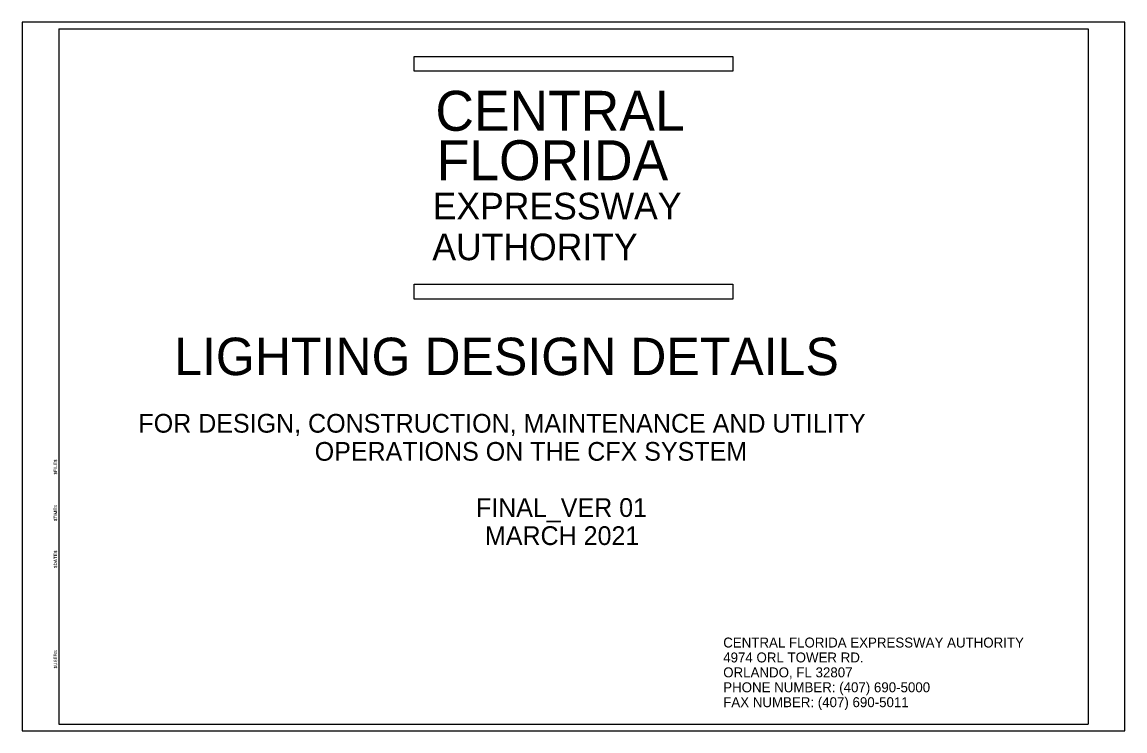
# Model space of a CAD drawing. Extents: x 1888.7 to 1905.2, y -90 to -79.4.
import ezdxf

# ---------------------------------------------------------------- set-up
doc = ezdxf.new("R2010")
doc.units = 0
for name, color, linetype in [('PlotBorder_dp', 7, 'Continuous'), ('SheetBorder_dp', 7, 'Continuous'), ('SignPanel', 7, 'Continuous'), ('TextLabel', 7, 'Continuous'), ('TextMisc', 7, 'Continuous'), ('TextStructures', 7, 'Continuous')]:
    doc.layers.add(name, color=color, linetype=linetype)

msp = doc.modelspace()

# ---------------------------------------------------------------- linework, layer by layer
at = {"layer": 'PlotBorder_dp'}
msp.add_lwpolyline([(1888.731, -90), (1905.231, -90), (1905.231, -79.4), (1888.731, -79.4)], close=True, dxfattribs=at)
at = {"layer": 'SheetBorder_dp'}
for p, q in [((1889.281, -79.5), (1889.281, -89.9)), ((1889.281, -79.5), (1904.681, -79.5)), ((1904.681, -79.5), (1904.681, -89.9)), ((1889.281, -89.9), (1904.681, -89.9))]:
    msp.add_line(p, q, dxfattribs=at)
at = {"layer": 'SignPanel'}
for points in [[(1894.598, -79.914), (1899.364, -79.914), (1899.364, -80.137), (1894.598, -80.137)], [(1894.598, -83.32), (1899.364, -83.32), (1899.364, -83.543), (1894.598, -83.543)]]:
    msp.add_lwpolyline(points, close=True, dxfattribs=at)

# ---------------------------------------------------------------- texts
for s, height, p in [('CENTRAL', 0.5974, (1894.915, -81.026)), ('FLORIDA', 0.5974, (1894.935, -81.765)), ('EXPRESSWAY', 0.3976, (1894.874, -82.351)), ('AUTHORITY', 0.3976, (1894.869, -82.961))]:
    msp.add_text(s, height=height, dxfattribs=at).set_placement(p)
at = {"layer": 'TextLabel'}
msp.add_text('LIGHTING DESIGN DETAILS', height=0.56, dxfattribs=at).set_placement((1891.006, -84.68))
at = {"layer": 'TextMisc'}
for s, p in [('$FILE$', (1889.256, -86.165)), ('$TIME$', (1889.256, -86.865)), ('$DATE$', (1889.256, -87.565)), ('$USER$', (1889.256, -89.065))]:
    msp.add_text(s, height=0.05, rotation=90, dxfattribs=at).set_placement(p)
at = {"layer": 'TextStructures'}
for s, height, p in [('FOR DESIGN, CONSTRUCTION, MAINTENANCE AND UTILITY', 0.28, (1890.472, -85.54)), ('OPERATIONS ON THE CFX SYSTEM', 0.28, (1893.109, -85.96)), ('FINAL_VER 01', 0.28, (1895.521, -86.8)), ('MARCH 2021', 0.28, (1895.656, -87.22)), ('CENTRAL FLORIDA EXPRESSWAY AUTHORITY', 0.14875, (1899.221, -88.753)), ('4974 ORL TOWER RD.', 0.14875, (1899.221, -88.976)), ('ORLANDO, FL 32807', 0.14875, (1899.221, -89.199)), ('PHONE NUMBER: (407) 690-5000', 0.14875, (1899.221, -89.422)), ('FAX NUMBER: (407) 690-5011', 0.14875, (1899.221, -89.645))]:
    msp.add_text(s, height=height, dxfattribs=at).set_placement(p)

doc.saveas('drawing.dxf')
